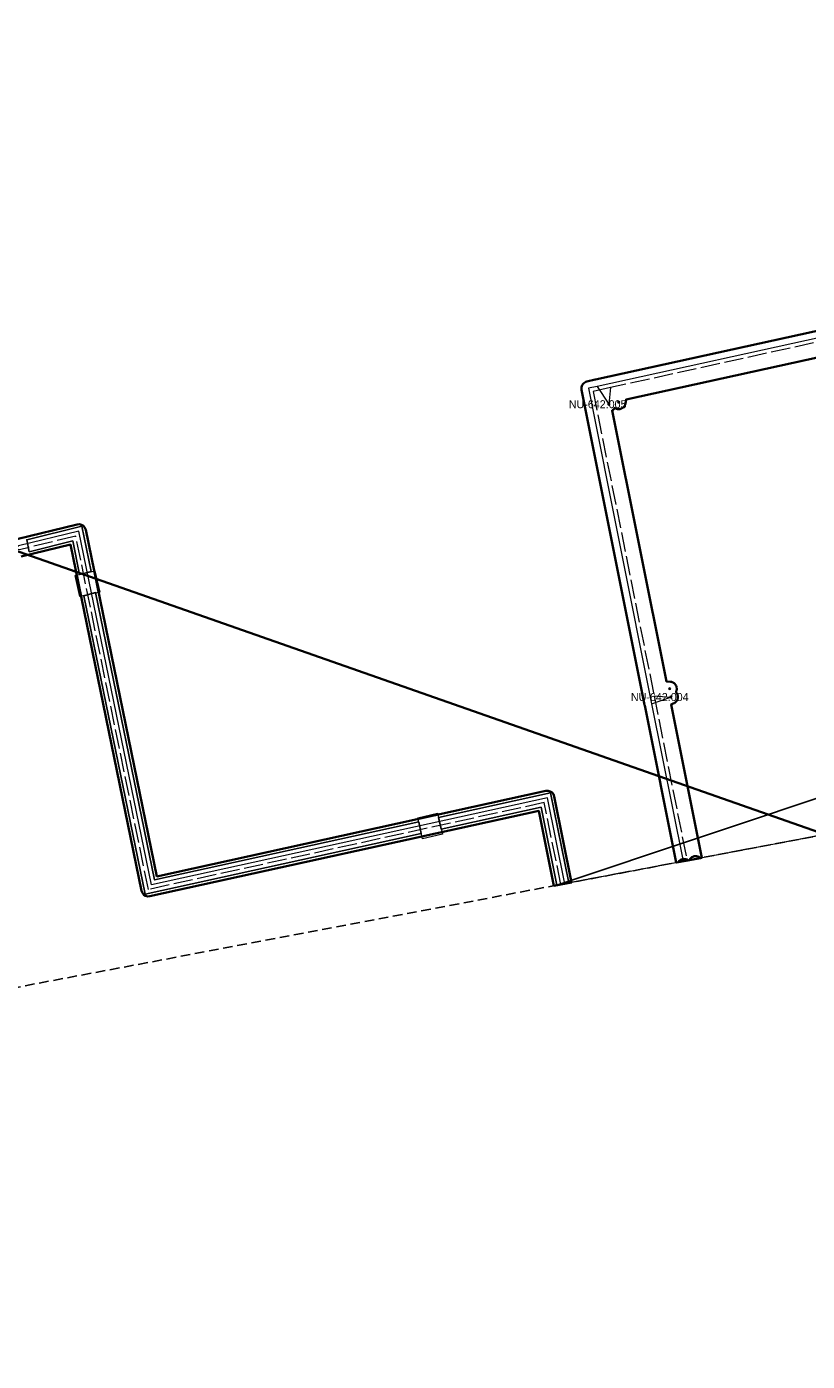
# Model space of a CAD drawing. Extents: x -452602 to -451136, y -1100088 to -1099653.
# Drawn here: x -452373.5 to -452295.4, y -1100088.3 to -1099954.9 of the extents above; entities that cross this region are included whole.
import ezdxf

# ---------------------------------------------------------------- set-up
doc = ezdxf.new("R2010")
doc.units = 0
doc.header["$LTSCALE"] = 0.32
doc.header["$PDMODE"] = 32
doc.header["$PDSIZE"] = 0.16
doc.linetypes.add('LONG_DASHED', pattern=[7.5, 6, -1.5])
doc.linetypes.add('MEDIUM_DASHED', pattern=[4.5, 3, -1.5])
for name, color, linetype, lineweight in [('2', 7, 'Continuous', 13), ('3', 7, 'Continuous', 25), ('62', 7, 'MEDIUM_DASHED', 25), ('8', 7, 'Continuous', 35)]:
    doc.layers.add(name, color=color, linetype=linetype, lineweight=lineweight)
doc.layers.add('4', color=7, linetype='Continuous')

msp = doc.modelspace()

# ---------------------------------------------------------------- linework, layer by layer
at = {"layer": '2'}
for p, q in [((-452264.85, -1099979.478), (-452316.457, -1099990.813)), ((-452316.457, -1099990.813), (-452315.284, -1099992.593)), ((-452311.008, -1100022.548), (-452309.078, -1100021.865)), ((-452311.007, -1100022.548), (-452307.856, -1100038.284))]:
    msp.add_line(p, q, dxfattribs=at)
at = {"layer": '2', "linetype": 'LONG_DASHED'}
for p, q in [((-452264.35, -1099979.776), (-452315.103, -1099990.927)), ((-452315.103, -1099990.927), (-452315.284, -1099992.593)), ((-452310.763, -1100021.733), (-452307.463, -1100038.21)), ((-452310.762, -1100021.732), (-452309.078, -1100021.865))]:
    msp.add_line(p, q, dxfattribs=at)
at = {"layer": '2'}
for points in [[(-452316.457, -1099990.813), (-452317.324, -1099991.004), (-452311.007, -1100022.548)], [(-452230.97, -1100011.922), (-452233.825, -1100000.337), (-452251.193, -1100003.897), (-452251.762, -1100001.19), (-452256.853, -1100002.269), (-452256.282, -1100004.975), (-452267.969, -1100007.37), (-452280.097, -1100021.193), (-452282.212, -1100019.502), (-452285.734, -1100023.486), (-452283.859, -1100025.484), (-452292.551, -1100035.39), (-452319.689, -1100040.522), (-452321.428, -1100031.934), (-452361.009, -1100040.625), (-452368.273, -1100005.285), (-452374.31, -1100006.761), (-452374.659, -1100007.061)]]:
    msp.add_lwpolyline(points, dxfattribs=at)
at = {"layer": '2', "linetype": 'LONG_DASHED'}
for points in [[(-452315.103, -1099990.927), (-452316.854, -1099991.311), (-452310.763, -1100021.733)], [(-452231.354, -1100012.033), (-452234.13, -1100000.807), (-452251.502, -1100004.37), (-452252.071, -1100001.664), (-452256.379, -1100002.578), (-452255.809, -1100005.287), (-452267.758, -1100007.734), (-452280.049, -1100021.745), (-452282.164, -1100020.052), (-452285.193, -1100023.478), (-452283.32, -1100025.473), (-452291.913, -1100035.269), (-452320.083, -1100040.596), (-452321.74, -1100032.412), (-452361.32, -1100041.103), (-452368.581, -1100005.774), (-452374.217, -1100007.149), (-452374.659, -1100007.061)]]:
    msp.add_lwpolyline(points, dxfattribs=at)
at = {"layer": '3'}
for points in [[(-452368.203, -1100009.61), (-452368.889, -1100006.26), (-452373.242, -1100007.333), (-452373.488, -1100006.148), (-452367.964, -1100004.798), (-452367.033, -1100009.331)], [(-452334.035, -1100035.521), (-452361.63, -1100041.58), (-452367.793, -1100011.741), (-452366.601, -1100011.429), (-452360.699, -1100040.147), (-452334.295, -1100034.349)]]:
    msp.add_lwpolyline(points, close=True, dxfattribs=at)
at = {"layer": '3', "lineweight": 13}
for points in [[(-452368.169, -1100011.829), (-452368.662, -1100009.718), (-452366.682, -1100009.255), (-452366.189, -1100011.366)], [(-452333.902, -1100036.048), (-452334.395, -1100033.937), (-452332.414, -1100033.474), (-452331.921, -1100035.585)]]:
    msp.add_lwpolyline(points, close=True, dxfattribs=at)
at = {"layer": '3'}
msp.add_lwpolyline([(-452231.993, -1100011.115), (-452320.476, -1100040.671), (-452322.051, -1100032.889), (-452332.044, -1100035.084), (-452332.305, -1100033.912), (-452321.116, -1100031.456), (-452319.296, -1100040.447), (-452320.476, -1100040.671)], dxfattribs=at)
at = {"layer": '4'}
for p in [(-452315.284, -1099992.593), (-452314.306, -1099992.387), (-452309.192, -1100021.025), (-452309.078, -1100021.865)]:
    msp.add_point(p, dxfattribs=at)
at = {"layer": '62'}
msp.add_lwpolyline([(-451137.485, -1099816.961), (-452572.169, -1100088.267), (-452602.314, -1099919.678), (-451137.485, -1099652.838), (-451136.368, -1099701.963)], close=True, dxfattribs=at)
at = {"layer": '8'}
for points in [[(-452308.494, -1100020.979), (-452308.492, -1100021.025), (-452308.494, -1100021.071), (-452308.498, -1100021.116), (-452308.506, -1100021.162), (-452308.516, -1100021.206), (-452308.529, -1100021.25), (-452308.545, -1100021.293), (-452308.564, -1100021.335), (-452308.583, -1100021.37), (-452308.551, -1100021.403), (-452308.522, -1100021.439), (-452308.496, -1100021.476), (-452308.471, -1100021.515), (-452308.45, -1100021.555), (-452308.431, -1100021.597), (-452308.415, -1100021.64), (-452308.402, -1100021.684), (-452308.391, -1100021.728), (-452308.384, -1100021.774), (-452308.379, -1100021.819), (-452308.378, -1100021.865), (-452308.379, -1100021.911), (-452308.384, -1100021.956), (-452308.391, -1100022.002), (-452308.402, -1100022.046), (-452308.415, -1100022.09), (-452308.431, -1100022.133), (-452308.45, -1100022.175), (-452308.471, -1100022.215), (-452308.496, -1100022.254), (-452308.522, -1100022.291), (-452308.551, -1100022.326), (-452308.583, -1100022.36), (-452308.616, -1100022.391), (-452308.652, -1100022.42), (-452308.689, -1100022.447), (-452308.728, -1100022.471), (-452308.768, -1100022.493), (-452308.81, -1100022.512), (-452308.844, -1100022.525), (-452309.059, -1100022.601), (-452305.989, -1100037.931), (-452308.544, -1100038.414), (-452311.688, -1100022.713), (-452311.69, -1100022.702), (-452311.694, -1100022.686), (-452311.696, -1100022.676), (-452311.701, -1100022.64), (-452318.01, -1099991.141), (-452318.023, -1099991.021), (-452318.016, -1099990.901), (-452317.988, -1099990.783), (-452317.94, -1099990.673), (-452317.875, -1099990.572), (-452317.792, -1099990.484), (-452317.696, -1099990.411), (-452317.589, -1099990.356), (-452317.474, -1099990.32), (-452316.638, -1099990.137), (-452316.634, -1099990.136), (-452316.607, -1099990.13), (-452265, -1099978.795)], [(-452265.134, -1099981.484), (-452313.559, -1099992.123), (-452313.614, -1099992.49), (-452313.62, -1099992.523), (-452313.63, -1099992.568), (-452313.643, -1099992.612), (-452313.659, -1099992.655), (-452313.678, -1099992.696), (-452313.7, -1099992.737), (-452313.724, -1099992.776), (-452313.751, -1099992.813), (-452313.78, -1099992.848), (-452313.811, -1099992.882), (-452313.845, -1099992.913), (-452313.88, -1099992.942), (-452313.917, -1099992.969), (-452313.956, -1099992.993), (-452313.997, -1099993.015), (-452314.038, -1099993.034), (-452314.081, -1099993.05), (-452314.125, -1099993.063), (-452314.17, -1099993.073), (-452314.215, -1099993.081), (-452314.26, -1099993.085), (-452314.306, -1099993.087), (-452314.352, -1099993.085), (-452314.398, -1099993.081), (-452314.443, -1099993.073), (-452314.487, -1099993.063), (-452314.531, -1099993.05), (-452314.574, -1099993.034), (-452314.616, -1099993.015), (-452314.656, -1099992.993), (-452314.694, -1099992.969), (-452314.702, -1099992.982), (-452314.728, -1099993.019), (-452314.757, -1099993.055), (-452314.789, -1099993.088), (-452314.822, -1099993.12), (-452314.858, -1099993.149), (-452314.895, -1099993.175), (-452314.934, -1099993.2), (-452314.945, -1099993.206), (-452309.521, -1100020.295), (-452309.133, -1100020.328), (-452309.101, -1100020.331), (-452309.056, -1100020.339), (-452309.011, -1100020.349), (-452308.967, -1100020.362), (-452308.924, -1100020.378), (-452308.883, -1100020.397), (-452308.842, -1100020.419), (-452308.803, -1100020.443), (-452308.766, -1100020.47), (-452308.731, -1100020.499), (-452308.697, -1100020.53), (-452308.666, -1100020.563), (-452308.637, -1100020.599), (-452308.61, -1100020.636), (-452308.586, -1100020.675), (-452308.564, -1100020.715), (-452308.545, -1100020.757), (-452308.529, -1100020.8), (-452308.516, -1100020.844), (-452308.506, -1100020.888), (-452308.498, -1100020.934)], [(-452374.477, -1100006.081), (-452368.439, -1100004.605), (-452368.215, -1100004.588), (-452367.998, -1100004.642), (-452367.808, -1100004.762), (-452367.667, -1100004.935), (-452367.587, -1100005.145), (-452360.467, -1100039.789), (-452321.578, -1100031.25), (-452321.357, -1100031.237), (-452321.143, -1100031.294), (-452320.957, -1100031.415), (-452320.819, -1100031.587), (-452320.741, -1100031.795), (-452319.001, -1100040.392), (-452320.771, -1100040.726), (-452322.284, -1100033.248), (-452361.169, -1100041.786), (-452361.39, -1100041.799), (-452361.603, -1100041.742), (-452361.789, -1100041.622), (-452361.927, -1100041.45), (-452362.005, -1100041.243), (-452369.12, -1100006.626), (-452374.051, -1100007.829)], [(-452374.913, -1100007.111), (-452293.667, -1100035.601)], [(-452308.349, -1100038.377), (-452308.328, -1100038.342), (-452308.248, -1100038.25), (-452308.154, -1100038.173), (-452308.049, -1100038.114), (-452307.934, -1100038.074), (-452307.814, -1100038.054), (-452307.693, -1100038.055), (-452307.574, -1100038.077), (-452307.46, -1100038.12), (-452307.355, -1100038.181), (-452307.347, -1100038.188), (-452308.349, -1100038.377), (-452307.224, -1100038.165), (-452307.217, -1100038.148), (-452307.153, -1100038.046), (-452307.073, -1100037.956), (-452306.978, -1100037.882), (-452306.872, -1100037.825), (-452306.757, -1100037.787), (-452306.638, -1100037.769), (-452306.518, -1100037.772), (-452306.4, -1100037.796), (-452306.287, -1100037.839), (-452306.184, -1100037.901), (-452306.121, -1100037.956), (-452307.224, -1100038.165)]]:
    msp.add_lwpolyline(points, dxfattribs=at)

# ---------------------------------------------------------------- texts
at = {"layer": '4'}
for s, p in [('NU-642.005', (-452319.284, -1099992.993)), ('NU-642.004', (-452313.078, -1100022.265))]:
    msp.add_text(s, height=0.8, dxfattribs=at).set_placement(p)

doc.saveas('drawing.dxf')
